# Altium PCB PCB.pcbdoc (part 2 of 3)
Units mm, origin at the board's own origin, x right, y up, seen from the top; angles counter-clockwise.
Board outline 65.2 x 64.45 mm, 2 copper layers (Top Layer, Bottom Layer); 194 components, 135 nets, 803 pads, 401 vias.
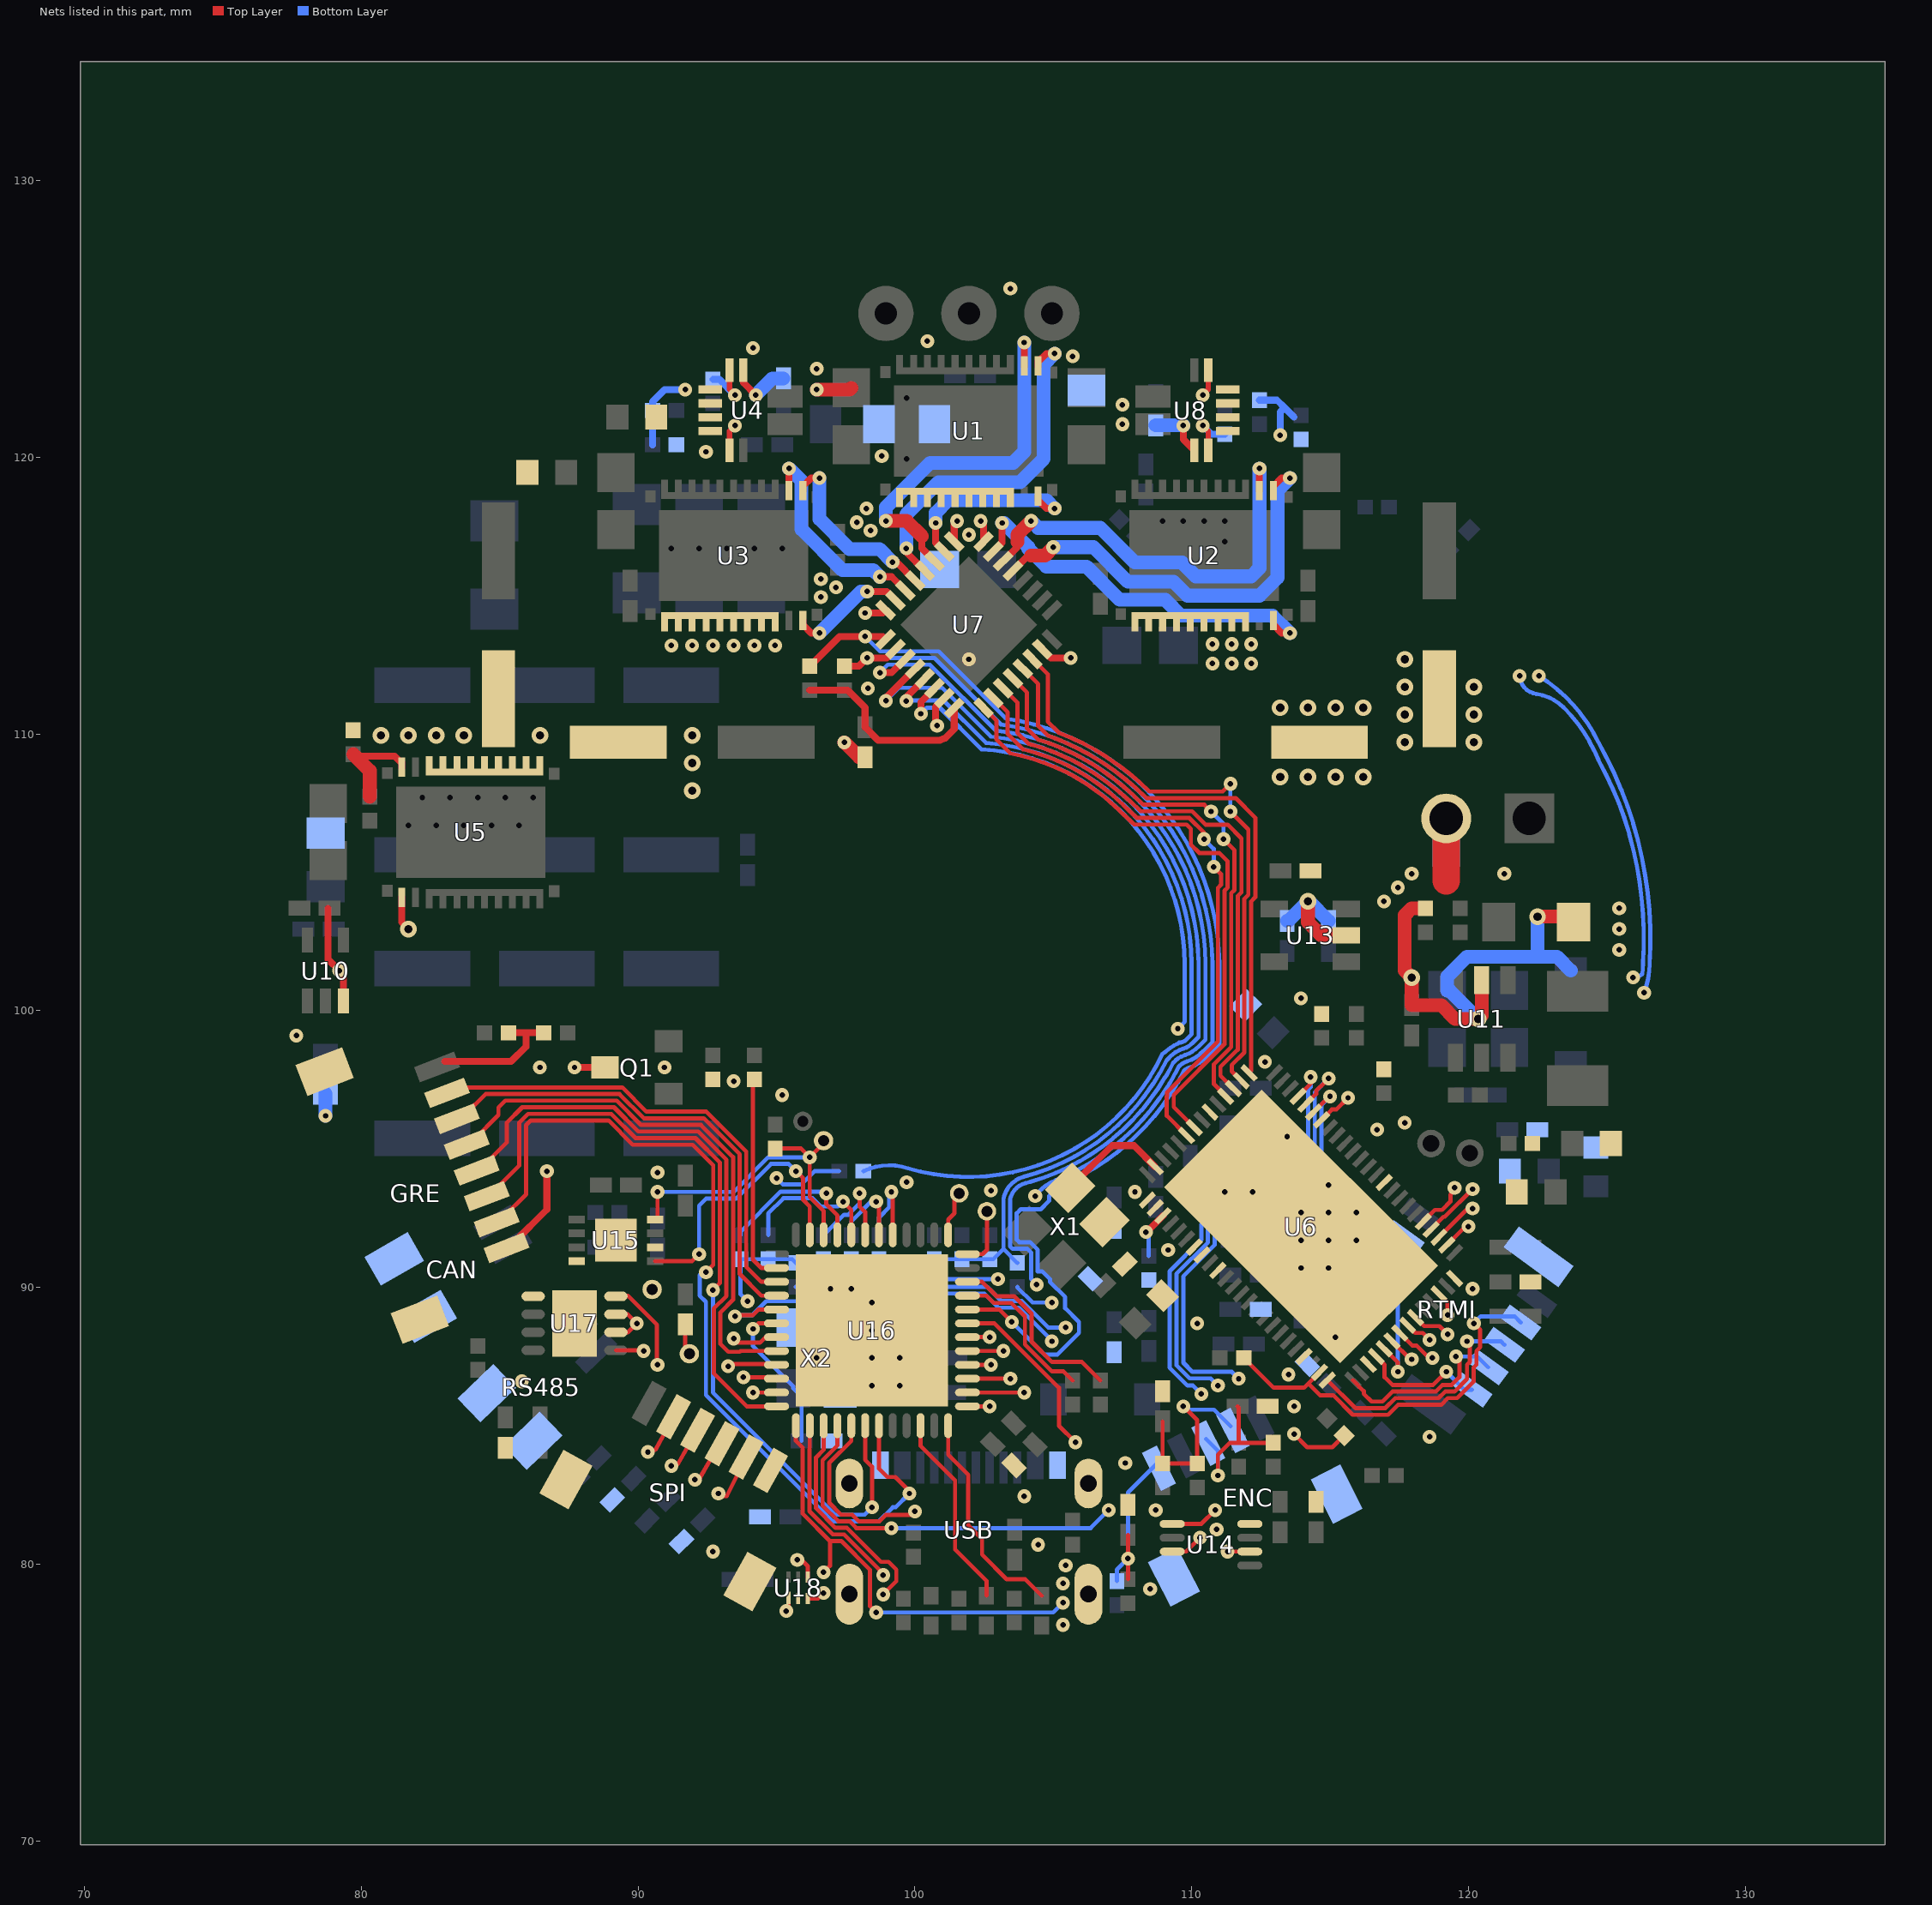
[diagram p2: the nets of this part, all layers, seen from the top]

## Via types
v1: diameter 0.5, hole 0.2, Top Layer to Bottom Layer, 297 vias
v2: diameter 0.6, hole 0.3, Top Layer to Bottom Layer, 104 vias

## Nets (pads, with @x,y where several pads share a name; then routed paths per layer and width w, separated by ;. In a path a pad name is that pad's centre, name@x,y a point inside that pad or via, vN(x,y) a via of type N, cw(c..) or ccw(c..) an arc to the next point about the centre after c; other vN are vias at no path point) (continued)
CAN_RX: pad.4 R58.1 U15.4 U16.46 | length 12.4
  Top Layer w0.15: U15.4@90.618,92.45 90.7,92.532 v1(90.7,93.45) ; R58.1@94.95,95.017 95.883,95.017 v1(96.2,94.7) ; U16.46@96.7,91.899 96.7,92.762 96.2,93.262 v1(96.2,94.7) ; pad.4@96.7,95.45 96.7,95.2 v1(96.2,94.7)
  Bottom Layer w0.15: v1(90.7,93.45) 93.45,93.45 94.7,94.7 v1(96.2,94.7)
CAN_TX: U16.47 | length 10.2
  Top Layer w0.15: 90.618,90.95 91.95,90.95 v1(92.2,91.2) ; v1(95.7,94.2) 95.961,93.939 95.961,93.163 96.2,92.924 U16.47@96.2,91.899
  Bottom Layer w0.15: v1(92.2,91.2) 92.2,92.95 92.461,93.211 93.549,93.211 94.799,94.461 95.439,94.461 v1(95.7,94.2)
CS_2: SPI.2 U16.25 | length 19.2
  Top Layer w0.15: v1(90.35,84.05) 90.623,84.129 SPI.2@91.31,85.374 ; U16.25@101.95,85.7 v1(102.7,85.7)
  Mid-Layer 1 w0.15: v1(90.35,84.05) 93.613,84.05 96.707,80.957 98.757,80.957 98.891,80.823 99.634,80.823 102.7,83.889 v1(102.7,85.7)
CSNA: R16.1 U6.19 | length 38.7
  Top Layer w0.15: U6.19@118.369,92.377 118.793,92.8 119.05,92.8 119.35,93.1 119.35,93.35 119.5,93.5 v1(119.5,93.6)
  Mid-Layer 2 w0.15: v1(113.2,120.8) 113.45,121.05 cw(c101.978,101.874) 120.55,114.3 cw(c116.909,111.333) 121.3,113 cw(c121.072,112.833) 121.331,112.719 ccw(c121.928,112.122) 121.149,112.447 ccw(c121.928,112.122) 121.194,111.704 ccw(c121.928,112.122) 121.261,111.603 ccw(c122.679,112.705) 121.7,111.2 ccw(c122.453,112.357) 122.2,111 cw(c121.82,108.962) 122.86,110.755 cw(c122.13,109.771) 123.193,110.381 cw(c122.707,110.102) 123.214,110.34 cw(c113.922,107.883) 123.264,110.143 cw(c113.922,107.883) 123.533,107.949 123.533,97.633 120.899,94.999 120.899,94.663 120.311,94.075 119.975,94.075 v1(119.5,93.6)
  Bottom Layer w0.25: R16.1@112.45,122.066 113.084,122.066 113.355,121.795 ; v1(113.2,120.8) 113.2,121.641 113.355,121.795 ; 113.7,121.45 113.355,121.795
CSNC: R11.1 U6.17 | length 63.6
  Top Layer w0.15: U6.17@118.935,91.811 119.974,92.85 v1(120.15,92.85)
  Mid-Layer 2 w0.15: v1(91.7,122.45) 93.02,122.45 ; 93.023,122.448 93.02,122.45 ; v1(120.15,92.85) 120.65,93.35 120.65,93.738 121.377,94.465 121.377,94.777 124.011,97.411 124.011,107.95 ccw(c113.922,107.883) 122.95,112.387 cw(c124.124,113.374) 122.8,112.6 ccw(c101.792,101.474) 108.291,124.341 ccw(c114.792,117.757) 108.25,124.3 106.85,122.9 98.662,122.9 97.612,123.95 94.862,123.95 93.662,122.75 93.32,122.75 93.02,122.45
  Bottom Layer w0.25: 90.517,120.45 R11.1@90.517,121.7 90.517,122.017 90.95,122.45 v1(91.7,122.45)
CSPA: U6.18 U8.11 | length 40.6
  Top Layer w0.15: U6.18@118.652,92.094 118.652,92.102 119.1,92.55 119.15,92.55 v1(120.15,93.55)
  Top Layer w0.2: v1(110.4,122.25) 110.6,122.45 U8.11@110.6,123.15
  Mid-Layer 2 w0.15: v1(110.4,122.25) 110.8,122.65 cw(c110.8,111.676) 110.867,122.65 cw(c101.865,101.702) 121,114.1 ; v1(120.15,93.55) 120.15,93.576 121.138,94.564 121.138,94.888 123.772,97.522 123.772,107.95 ccw(c113.922,107.883) 123.496,110.199 ccw(c113.921,107.883) 123.44,110.42 ccw(c122.707,110.102) 123.4,110.5 ccw(c122.13,109.771) 122.45,111.2 cw(c122.897,113.197) 121.45,111.75 cw(c121.928,112.122) 121.5,112.55 ccw(c121.219,112.831) 121.55,113.05 ccw(c116.681,111.169) 121,114.1
CSPC: U4.11 U6.16 | length 62.9
  Top Layer w0.15: U6.16@119.218,91.528 119.89,92.2 v1(120,92.2)
  Top Layer w0.2: U4.11@93.3,120.25 93.3,120.95 v1(93.5,121.15)
  Mid-Layer 1 w0.15: v1(93.5,121.15) 92.95,121.7 92.95,122.7 94.15,123.9 v1(94.15,123.95)
  Mid-Layer 2 w0.15: v1(94.15,123.95) 94.524,123.95 94.774,124.2 97.7,124.2 98.75,123.15 106.75,123.15 108.211,124.611 cw(c101.763,101.367) 122.95,112.9 cw(c113.922,107.883) 124.25,107.95 124.25,97.312 121.616,94.678 121.616,94.366 120.889,93.639 120.889,93.251 120.65,93.012 120.65,92.65 120.2,92.2 v1(120,92.2)
CUR_SENSE_FAULT: U16.29 U18.4 | length 15.2
  Top Layer w0.15: v1(95.75,80.15) 95.9,80.15 96.129,79.921 U18.4@96.129,79.533 ; U16.29@101.899,87.701 v1(103.199,87.701)
  Mid-Layer 2 w0.15: v1(95.75,80.15) 95.75,83.25 96.95,84.45 100.45,84.45 101.7,85.7 101.7,86.825 102.575,87.7 v1@103.199,87.7
DBGSPI_CS: R43.1 RTMI.4 U6.75 | length 14.6
  Top Layer w0.15: R43.1@111.883,87.45 112.96,86.373 114.062,86.373 114.229,86.539 ; U6.75@114.622,86.932 114.229,86.539 ; v1(120.2,88.7) 120.427,88.473 120.427,87.838 120.289,87.7 120.289,87.201 120.189,87.101 120.189,86.588 119.596,85.995 119.258,85.995 119.019,85.756 117.457,85.756 117.096,85.395 115.821,85.395 115.114,86.102 114.635,86.102 114.229,86.508 114.229,86.539
  Bottom Layer w0.15: v1(120.2,88.7) 120.45,88.95 121.672,88.95 RTMI.4@121.891,88.731
DBGSPI_MISO: RTMI.10 U6.4 | length 4.6
  Top Layer w0.15: U6.4@116.672,87.498 116.973,87.197 116.973,86.752 117.252,86.473 118.723,86.473 v1(119.2,86.95)
  Bottom Layer w0.15: v1(119.2,86.95) 119.846,86.304 RTMI.10@120.128,86.304
DBGSPI_MOSI: RTMI.8 | length 6.7
  Top Layer w0.15: 115.824,86.649 116.223,86.251 116.223,86.152 116.502,85.873 116.898,85.873 117.259,86.234 118.822,86.234 119.06,86.473 119.398,86.473 119.677,86.752 119.677,87.373 v1(119.55,87.5)
  Bottom Layer w0.15: v1(119.55,87.5) 120.328,87.5 RTMI.8@120.716,87.113
DBGSPI_SCK: RTMI.6 U6.76 | length 8.8
  Top Layer w0.15: U6.76@114.905,86.649 115.92,85.634 116.997,85.634 117.358,85.995 118.921,85.995 119.159,86.234 119.497,86.234 119.95,86.687 119.95,87.2 120.05,87.3 120.05,87.95 v1(119.95,88.05)
  Bottom Layer w0.15: v1(119.95,88.05) 121.175,88.05 RTMI.6@121.304,87.922
DBGSPI_TRG: RTMI.3 U6.5 | length 6.3
  Top Layer w0.15: U6.5@116.955,87.781 117.45,87.286 v1(117.45,86.95)
  Bottom Layer w0.15: v1(117.45,86.95) 117.45,89.7 118.067,90.317 118.067,91.405 RTMI.3@117.684,91.787
DE: U16.9 U17.2 U17.3 | length 8.1
  Top Layer w0.15: U17.2@89.195,88.375 89.625,88.375 v1(89.95,88.7) 89.625,89.025 U17.3@89.195,89.025 ; v1(93.25,87.15) 93.327,87.227 94.973,87.227 U16.9@95.001,87.2
  Mid-Layer 2 w0.15: v1(89.95,88.7) 89.95,88.625 91.675,86.9 93.125,86.9 93.402,87.177 93.277,87.177 v1(93.25,87.15)
DIAG_1: U16.22 | length 7.1
  Top Layer w0.15: U16.22@100.2,85.001 100.2,84.275 101.45,83.025 101.45,80.525 102.584,79.39 102.584,78.854
DIAG_2: U16.24 | length 7.9
  Top Layer w0.15: U16.24@101.201,84.951 101.201,83.95 101.928,83.223 101.928,81.397 102.427,80.898 102.427,80.341 103.318,79.45 103.988,79.45 104.584,78.854
DVDD: U7.24 | length 7.3
  Top Layer w0.25: 98.2,110.245 98.673,109.773 100.902,109.773 101.096,109.851 101.42,110.174 U7.24@101.42,110.945
  Top Layer w0.254: 96.2,111.584 97.566,111.584 98.2,110.95 98.2,110.245
ENC_A: U6.35 U14.7 | length 23.5
  Top Layer w0.15: U14.7@109.297,80.45 109.8,80.45 v1(110.3,80.95) ; U6.35@113.844,96.902 114.3,97.358 v1(114.3,97.6)
  Mid-Layer 1 w0.15: v1(110.3,80.95) 109.95,80.95 109.2,81.7 109.2,82.7 110.35,83.85 v1(110.35,86.15)
  Bottom Layer w0.15: v1(110.35,86.15) 110.05,86.45 109.849,86.45 109.2,87.099 109.2,90.576 110.35,91.725 110.35,92.275 110.752,92.678 112.34,92.678 114.211,94.549 114.211,97.149 114.3,97.238 v1(114.3,97.6)
ENC_A_5: ENC.5 R54.1 | length 6.4
  Top Layer w0.15: 107.7,79.45 v1(107.7,80.2) 107.7,81.05
  Bottom Layer w0.15: R54.1@107.3,79.383 107.3,79.8 v1(107.7,80.2) 107.7,82.581 ENC.5@108.737,83.619
ENC_B: U6.34 U14.5 | length 23.3
  Top Layer w0.15: U14.5@109.297,81.45 110.35,81.45 v1(110.85,81.95) ; U6.34@114.127,96.619 114.5,96.992 114.5,97.1 v1@114.8,97.4
  Mid-Layer 1 w0.15: v1(110.85,81.95) 111.45,82.55 111.45,86.2 111.2,86.45 v1(110.95,86.45)
  Bottom Layer w0.15: v1(110.95,86.45) 110.689,86.711 109.926,86.711 109.45,87.187 109.45,90.488 110.589,91.627 110.589,92.177 110.851,92.439 112.439,92.439 114.45,94.45 114.45,97.05 v1(114.95,97.55)
ENC_B_5: ENC.3 R52.1 | length 5.8
  Top Layer w0.15: v1(110.95,83.2) 110.95,83.95 111.383,84.383 111.7,84.383 ; 111.655,85.7 111.7,85.655 111.7,84.383 ; R52.1@112.95,84.383 111.7,84.383
  Bottom Layer w0.15: ENC.3@110.519,84.527 110.95,84.096 v1(110.95,83.2)
ENC_I: U6.33 U14.2 | length 23
  Top Layer w0.15: v1(111.3,80.45) U14.2@112.103,80.45 ; U6.33@114.41,96.336 114.973,96.9 v1(115,96.9)
  Mid-Layer 1 w0.15: v1(111.3,80.45) 111.7,80.85 v1(111.7,86.7)
  Bottom Layer w0.15: v1(111.7,86.7) 111.45,86.95 110.025,86.95 109.7,87.275 109.7,90.394 109.697,90.397 110.828,91.528 110.828,92.078 110.95,92.2 112.538,92.2 114.689,94.351 114.689,96.589 v1(115,96.9)
ENC_I_5: ENC.2 R50.1 R51.1 | length 7.1
  Top Layer w0.15: 108.95,85.155 R51.1@108.95,83.633 R50.1@110.2,83.633 110.2,85.2 v1(109.7,85.7)
  Bottom Layer w0.15: v1(109.7,85.7) 109.82,85.58 110.811,85.58 ENC.2@111.41,84.981
F_CLOCK: U6.51 X1.3 | length 4
  Top Layer w0.25: X1.3@105.609,93.597 105.609,93.609 107.124,95.124 107.915,95.124 U6.51@108.682,94.357
F_CS: R41.1 U6.6 U16.16 | length 36
  Top Layer w0.15: U16.16@97.2,85.001 97.2,84.288 96.664,83.752 96.664,82.112 97.23,81.546 97.638,81.546 97.885,81.3 v1(99.15,81.3) ; v1(113.7,84.7) 114.177,84.223 115.085,84.223 R41.1@115.506,84.644 ; U6.6@117.238,88.063 117.902,87.4 v1(117.95,87.4)
  Mid-Layer 1 w0.15: v1(107,81.95) 107.639,81.95 108.894,80.695 108.894,80.395 109.821,79.468 110.314,79.468 ccw(c106.164,95.236) 114.205,81.052 ccw(c105.243,92.657) 115.611,82.289 115.611,84.224 ; v1(113.7,84.7) 113.775,84.7 114.252,84.223 115.473,84.223 ; 115.474,84.224 115.611,84.224 ; v1(117.95,87.4) 117.95,86.563 115.611,84.224
  Bottom Layer w0.15: v1(99.15,81.3) 106.35,81.3 v1(107,81.95)
F_EN: U6.55 U16.30 | length 10.7
  Top Layer w0.15: U16.30@101.9,88.2 v1(102.7,88.2)
  Top Layer w0.25: v1(108.35,92) 108.376,92 U6.55@108.965,92.589
  Mid-Layer 2 w0.15: v1(102.7,88.2) 102.7,88.95 103.5,89.75 103.5,90.6 103.85,90.95 107.3,90.95 v1(108.35,92)
  Bottom Layer w0.15: v1(108.35,92) 108.45,91.9 108.45,91.133
F_STATUS: U6.12 U16.31 | length 29.5
  Top Layer w0.15: U16.31@101.899,88.699 102.876,88.699 105.203,86.372 105.203,84.997 v1(105.8,84.4) ; U6.12@118.935,89.761 119.25,89.446 v1(119.25,89)
  Mid-Layer 2 w0.15: v1(105.8,84.4) 106.211,84.4 106.997,83.614 106.997,82.828 110.56,79.266 110.68,79.266 ccw(c107.165,90.535) 110.904,79.338 ccw(c107.165,90.535) 112.319,79.915 ccw(c104.576,93.074) 115.372,82.278 115.372,86.373 117.354,88.355 117.842,88.355 118.303,88.816 119.066,88.816 v1(119.25,89)
FA: R5.1 U8.6 U18.1 | length 84.9
  Top Layer w0.15: v1(95.35,78.3) 95.358,78.3 95.429,78.371 U18.1@95.429,78.804
  Top Layer w0.2: v1(110.4,121.15) 110.6,120.95 U8.6@110.6,120.25
  Mid-Layer 1 w0.15: v1(95.35,78.3) 96.45,78.3 96.85,77.9 ccw(c97.55,78.425) 97.55,77.55 105.1,77.55 v1(105.35,77.8) ; v1(105.35,79.3) 105.35,79.375 104.973,79.752 104.973,80.148 105.741,80.916 107.997,80.916 108.416,80.497 108.416,80.197 109.674,78.939 110.171,78.939 ccw(c106.166,95.232) 110.201,78.946 ccw(c106.164,95.236) 118.031,83.369 118.047,83.383 ccw(c103.592,100.652) 118.169,83.486 ccw(c103.594,100.65) 126.005,98.469 ccw(c103.594,100.65) 126.094,99.779 ccw(c125.025,99.025) 125.95,99.95 cw(c126.575,100.575) 125.7,100.45 cw(c126.575,100.575) v1(125.95,101.2)
  Mid-Layer 2 w0.15: v1(105.35,77.8) 104.873,78.277 104.873,78.798 105.35,79.275 v1(105.35,79.3) ; v1(110.4,121.15) 109.777,121.773 109.502,121.773 109.223,122.052 109.223,122.973 109.6,123.35 109.75,123.35 cw(c101.847,101.662) 121.45,113.85 cw(c119.681,112.525) v1(121.85,112.1)
  Bottom Layer w0.15: v1(121.85,112.1) ccw(c122.549,112.143) 122.45,111.45 cw(c122.2,109.7) 123.45,110.95 cw(c119.472,106.972) 124.7,109.05 cw(c113.901,102.968) 126.084,105.246 cw(c112.091,102.57) 126.311,101.714 ; v1(125.95,101.2) ccw(c125.95,101.7) 126.285,101.328 ccw(c123.694,101.7) 126.311,101.7
  Bottom Layer w0.25: v1(110.4,121.15) 110.716,120.834 R5.1@111.2,120.834
FC: R3.1 U4.6 U18.3 | length 97.2
  Top Layer w0.15: U18.3@96.129,78.759 96.509,78.759 v1(96.7,78.95)
  Top Layer w0.2: U4.6@93.3,123.15 93.3,122.45 v1(93.5,122.25)
  Mid-Layer 1 w0.15: v1(105.45,79.95) 105.45,80.287 105.84,80.677 107.898,80.677 108.177,80.398 108.177,80.098 109.575,78.7 110.2,78.7 ccw(c106.164,95.236) 118.2,83.2 ccw(c103.594,100.65) v1(126.35,100.65)
  Mid-Layer 2 w0.15: v1(93.5,122.25) 94.95,123.7 97.5,123.7 98.55,122.65 106.95,122.65 108.35,124.05 cw(c114.665,117.736) 108.37,124.07 ; v1(96.7,78.95) 96.7,78.25 ccw(c97.55,78.416) 97.55,77.55 98.575,77.55 99.686,78.661 103.824,78.661 105.113,79.95 v1(105.45,79.95) ; 108.37,124.07 cw(c101.84,101.643) 122.26,112.983 cw(c120.757,112.001) v1(122.55,112.1)
  Bottom Layer w0.15: v1(122.55,112.1) cw(c119.449,107.159) 124.7,109.7 cw(c112.091,102.57) 126.55,101.7 cw(c123.694,101.7) v1(126.35,100.65)
  Bottom Layer w0.25: R3.1@92.7,122.816 92.934,122.816 v1(93.5,122.25)
GHA: U2.1 U7.5 | length 15.5
  Top Layer w0.25: U7.5@103.541,115.894 104.097,116.45 ; U2.1@112.95,118.8 112.95,118.95 113.25,119.25 v1(113.55,119.25)
  Top Layer w0.5: 104.2,116.45 104.7,116.45 v1(105,116.75)
  Bottom Layer w0.5: v1(105,116.75) 106.45,116.75 107.7,115.5 109.35,115.5 109.85,115 112.45,115 113.1,115.65 113.1,118.8 v1(113.55,119.25)
GHB: U1.1 U7.12 | length 13
  Top Layer w0.25: v1(99.687,116.708) 99.687,116.566 U7.12@100.359,115.894 ; U1.1@104.45,123.3 104.45,123.45 104.75,123.75 v1(105.05,123.75)
  Bottom Layer w0.5: v1(99.687,116.708) 99.687,117.937 100.85,119.1 103.8,119.1 104.65,119.95 104.65,123.35 v1(105.05,123.75)
GHC: U3.1 U7.13 | length 6.7
  Top Layer w0.25: U3.1@95.95,118.8 95.95,118.95 96.25,119.25 v1(96.55,119.25) ; v1(99.192,116.213) 99.334,116.213 U7.13@100.006,115.541
  Bottom Layer w0.5: v1(96.55,119.25) 96.55,117.768 97.632,116.686 98.719,116.686 v1(99.192,116.213)
GLA: U2.22 U7.7 | length 14.1
  Top Layer w0.25: U7.7@102.834,116.602 103.152,116.92 v1(103.152,117.627) ; U2.22@112.95,114.1 112.95,113.95 113.25,113.65 v1(113.55,113.65)
  Bottom Layer w0.5: v1(103.152,117.627) 103.223,117.627 104.1,116.75 104.1,116.7 104.75,116.05 106.2,116.05 107.4,114.85 109.05,114.85 109.623,114.277 112.923,114.277 v1(113.55,113.65)
GLB: U1.22 U7.10 | length 7
  Top Layer w0.25: v1(100.748,117.627) 100.748,116.92 U7.10@101.066,116.602 ; U1.22@104.45,118.6 104.45,118.45 104.75,118.15 v1(105.05,118.15)
  Bottom Layer w0.5: v1(100.748,117.627) 100.748,117.998 101.2,118.45 104.75,118.45 v1(105.05,118.15)
GLBR: U5.22 | length 3.7
  Top Layer w0.25: 79.767,109.2 81.2,109.2 81.45,108.95 U5.22@81.45,108.8
  Top Layer w0.5: 79.7,109.267 79.767,109.2 80.3,108.667 80.3,107.733
GLC: U3.22 U7.15 | length 4.4
  Top Layer w0.25: U3.22@95.95,114.1 95.95,113.95 96.25,113.65 v1(96.55,113.65) ; v1(98.273,115.152) 98.98,115.152 U7.15@99.298,114.834
  Bottom Layer w0.5: v1(96.55,113.65) 98.052,115.152 v1(98.273,115.152)
GND: C18.1 C21.1 C23.1 C24.1 C25.2 C26.2 C27.2 C28.2 C29.2 C30.1 C31.1 C32.1 C37.1 C38.1 C42.1 C44.1 C46.1 C48.1 C50.1 C52.1 C54.1 C55.1 C57.1 C58.1 C59.1 C60.1 C64.1 C65.1 C66.1 C67.1 C68.1 C69.1 C70.1 C71.1 C72.1 C74.1 C76.1 C78.1 C80.1 C82.1 C84.1 C86.1 C87.1 C89.1 C91.1 CAN.3 CAN.4 ENC.6 ENC.7 GRE.9 GRE.10 pad.1@96.45,87.45 pad.1@96.95,89.95 pad.1@97.7,89.95 pad.1@98.45,86.45 pad.1@98.45,87.45 pad.1@98.45,88.45 pad.1@98.45,89.45 pad.1@99.45,86.45 pad.1@99.45,87.45 pad.1@101.95,112.7 pad.1@111.2,93.45 pad.1@112.2,93.45 pad.1@113.45,95.45 pad.1@113.95,90.7 pad.1@113.95,91.7 pad.1@113.95,92.7 pad.1@114.95,90.7 pad.1@114.95,91.7 pad.1@114.95,92.7 pad.1@114.95,93.7 pad.1@115.2,88.2 pad.1@115.95,91.7 pad.1@115.95,92.7 pad.3@90.504,89.926 R1.1 R2.1 R4.1 R6.1 R7.1 R12.1 R13.1 R14.1 R15.1 R26.1 R28.1 R42.1 R46.1 RS485.3 RS485.4 RTMI.5 RTMI.7 RTMI.9 RTMI.12 SPI.6 SPI.7 SPI.8 U1.12 U1.13 U1.14 U1.15 U1.16 U1.17 U1.18 U1.19 U1.20 U2.12 U2.13 U2.14 U2.15 U2.16 U2.17 U2.18 U2.19 U2.20 U3.12 U3.13 U3.14 U3.15 U3.16 U3.17 U3.18 U3.19 U3.20 U4.5 U4.7 U4.8 U4.9 U4.10 U5.1 U5.12 U5.13 U5.14 U5.15 U5.16 U5.17 U5.18 U5.19 U5.20 U6.3 U6.14 U6.24 U6.44 U6.53 U6.54 U6.59 U6.60 U6.62 U6.73 U6.77 U7.8 U7.9 U7.16 U7.23 U7.31 U8.5 U8.7 U8.8 U8.9 U8.10 U9.2 U10.3 U11.2 U13.2 U14.4 U15.2 U15.8 U15.9 U16.49 U17.5 U17.9 U18.2 USB.1 USB.12 USB.13 USB.14 USB.15 USB.16 X1.2 X2.2 X2.4 | length 45.4
  Top Layer w0.25: 78.79,103.7 78.79,101.86 v1(79.2,101.45) 79.35,101.3 U10.3@79.35,100.35 ; U5.1@81.45,104.1 81.45,103.2 v2(81.7,102.95) ; U4.5@93.8,123.15 93.8,122.7 v1(94.25,122.25) ; v1(98.202,114.374) 98.839,114.374 U7.16@98.945,114.48 ; v1(100.8,110.3) 100.75,110.35 100.75,110.982 U7.23@101.066,111.298 ; U7.9@101.42,116.955 101.42,117.592 v1(101.526,117.698) ; v1(102.374,117.698) 102.481,117.592 U7.8@102.481,116.955 ; U7.31@104.602,113.066 104.92,112.748 v1(105.627,112.748) ; v1(109.7,121.15) 109.7,120.65 U8.5@110.1,120.25
  Top Layer w0.5: v1(96.45,122.45) 97.64,122.45 97.7,122.51 ; v1(97.45,109.7) 97.995,109.155 C21.1@98.2,109.155 ; v2(114.2,103.95) 114.2,103.2 114.677,102.723 U13.2@115.588,102.723 ; R13.1@118.45,103.7 117.95,103.7 117.7,103.45 117.7,101.45 v2(117.95,101.2) 117.95,100.2 119.021,100.2 119.521,99.7 v2(120.35,99.7) 120.48,99.83 U11.2@120.48,101.1 ; v2(122.5,103.4) 123.35,103.4 C29.2@123.55,103.2
  Top Layer w1: 119.2,104.7 U9.2@119.2,106.95
  Mid-Layer 1 w1: 119.2,104.7 U9.2@119.2,106.95
  Bottom Layer w0.5: v1(78.7,96.2) C72.1@78.7,97 ; v1(94.25,122.25) 94.85,122.85 C24.1@95.25,122.85 ; C23.1@108.7,121.155 109.695,121.155 v1(109.7,121.15) ; C31.1@113.45,103.245 113.495,103.245 v2(114.2,103.95) 114.245,103.95 C30.1@114.95,103.245 ; v2(120.35,99.7) 119.32,100.73 119.23,100.73 119.23,101.23 119.95,101.95 122.462,101.95 ; v2(122.5,103.4) 122.5,101.988 122.462,101.95 ; 123.7,101.45 123.2,101.95 122.462,101.95
  Bottom Layer w1: 119.2,105.289 U9.2@119.2,106.95
  other v1: 108.5,79.1 92.7,80.45 104.45,80.7 110.9,81.25 108.7,81.95 103.95,82.45 107.6,83.65 118.6,84.6 113.7,85.7 85.8,86.6 113.5,86.85 110.2,88.7 120.15,89.95 109.15,91.35 107.95,93.45 102.75,93.5 99.7,93.8 90.7,94.15 116.7,95.7 117.7,95.95 95.2,96.95 93.45,97.45 86.45,97.95 90.95,97.95 112.65,98.15 77.65,99.1 113.95,100.45 125.45,102.2 125.45,102.95 125.45,103.7 116.95,103.95 117.45,104.45 117.95,104.95 121.3,104.95 98.3,111.65 110.75,112.55 111.45,112.55 112.15,112.55 91.2,113.2 91.95,113.2 92.7,113.2 93.45,113.2 94.2,113.2 94.95,113.2 110.75,113.25 111.45,113.25 112.15,113.25 96.6,114.95 97.15,115.3 96.6,115.6 101.95,117.2 98.4,117.35 97.9,117.65 98.25,118.15 98.8,120.05 92.45,120.2 107.5,121.2 107.5,121.9 96.45,123.2 105.7,123.65 100.45,124.2 103.45,126.1
  other v2: 91.95,107.95 113.2,108.45 114.2,108.45 115.2,108.45 116.2,108.45 91.95,108.95 117.7,109.7 120.2,109.7 80.7,109.95 81.7,109.95 82.7,109.95 83.7,109.95 86.45,109.95 91.95,109.95 117.7,110.7 120.2,110.7 113.2,110.95 114.2,110.95 115.2,110.95 116.2,110.95 117.7,111.7 120.2,111.7 117.7,112.7
GR_D0: GRE.2 U16.3 | length 17
  Top Layer w0.15: GRE.2@83.361,97.227 89.423,97.227 90.3,96.35 92.464,96.35 93.906,94.909 93.906,90.744 94.45,90.2 U16.3@95.001,90.2
GR_D1: GRE.3 U16.4 | length 17.1
  Top Layer w0.15: GRE.3@83.719,96.293 83.793,96.293 84.488,96.988 89.324,96.988 90.201,96.111 92.365,96.111 93.667,94.81 93.667,90.483 94.45,89.7 U16.4@95.001,89.7
GR_D2: GRE.4 U16.8 | length 20
  Top Layer w0.15: GRE.4@84.078,95.358 84.95,96.23 84.95,96.499 85.2,96.749 89.225,96.749 90.102,95.872 92.266,95.872 93.428,94.711 93.428,89.553 92.973,89.098 92.973,87.952 93.252,87.673 93.673,87.673 93.7,87.7 U16.8@95.001,87.701
GR_D3: GRE.5 U16.12 | length 21.5
  Top Layer w0.15: GRE.5@84.437,94.424 85.25,95.238 85.25,95.95 85.81,96.51 89.126,96.51 90.003,95.633 92.167,95.633 93.189,94.612 93.189,89.689 92.734,89.234 92.734,86.891 93.925,85.7 U16.12@95.001,85.699
GR_D4: GRE.6 U16.18 | length 30.1
  Top Layer w0.15: GRE.6@84.794,93.492 85.7,94.398 85.7,95.95 86.021,96.271 89.027,96.271 89.904,95.394 92.068,95.394 92.95,94.513 92.95,90.15 v1(92.7,89.9) ; U16.18@98.201,85.001 98.201,83.77 98.45,83.521 v1(98.45,82.05)
  Bottom Layer w0.15: v1(92.7,89.9) 92.7,86.2 97.115,81.785 97.931,81.785 98.185,81.785 v1(98.45,82.05)
GR_D5: GRE.7 U16.19 | length 32.7
  Top Layer w0.15: GRE.7@85.154,92.561 85.95,93.357 85.95,95.862 86.12,96.032 88.928,96.032 89.805,95.156 91.969,95.156 92.711,94.414 92.711,90.811 v1(92.45,90.55) ; U16.19@98.699,85.001 98.699,83.451 99.005,83.145 99.289,83.145 99.8,82.634 v1(99.8,82.55)
  Bottom Layer w0.15: v1(92.45,90.55) 92.45,90.67 92.223,90.443 92.223,89.702 92.45,89.475 92.45,86.112 97.016,81.546 98.696,81.546 99.2,82.05 99.3,82.05 v1(99.8,82.55)
GR_EN: R47.1 U16.2 | length 7.5
  Top Layer w0.15: R47.1@94.2,97.517 94.145,97.462 94.145,91.005 94.45,90.7 U16.2@95.001,90.7
GR_GND: GRE.8 Q1.3 | length 8.3
  Top Layer w0.25: GRE.8@85.513,91.627 86.7,92.814 v1(86.7,94.2) ; v1(87.7,97.95) Q1.3@88.8,97.95
  Mid-Layer 2 w0.25: v1(86.7,94.2) 87.7,95.2 v1(87.7,97.95)
GR_V: R48.1 R49.1 | length 4.9
  Top Layer w0.25: 83.004,98.162 85.412,98.162 85.95,98.7 85.95,99.186 85.936,99.2 ; R48.1@85.316,99.2 85.936,99.2 ; R49.1@86.584,99.2 85.936,99.2
IDRIVE_0: U16.41 | length 3.3
  Top Layer w0.15: v1(99.15,93.45) 99.199,93.401 U16.41@99.199,91.899
  Bottom Layer w0.15: 98.7,91.883 98.7,92.525 99.077,92.902 99.077,93.377 v1(99.15,93.45)
IDRIVE_18: U16.42 | length 2.9
  Top Layer w0.15: v1(98.6,93.1) 98.699,93.001 U16.42@98.699,91.899
  Bottom Layer w0.15: 97.7,91.883 97.7,92.387 98.413,93.1 v1(98.6,93.1)
IDRIVE_75: U16.43 | length 3.7
  Top Layer w0.15: v1(98,93.4) 98,92.925 98.201,92.724 U16.43@98.201,91.899
  Bottom Layer w0.15: 96.7,91.883 97.44,92.623 97.598,92.623 98,93.025 v1(98,93.4)
INHA: U6.46 U7.25 | length 22.3
  Top Layer w0.15: U7.25@102.48,110.945 102.95,110.475 102.95,109.8 103.45,109.3 cw(c102.011,101.708) 105.814,108.435 cw(c100.427,99.477) 106.875,107.703 cw(c94.744,93.694) 107.848,106.798 107.922,106.728 109.816,106.728 109.973,106.572 109.973,106.002 110.275,105.7 111,105.7 111.3,105.4 111.3,104.452 111.189,104.341 111.189,102.211 111.189,98.789 109.35,96.95 109.35,96.517 U6.46@110.096,95.771
INHB: U6.41 U7.27 | length 20.8
  Top Layer w0.15: U7.27@103.187,111.652 103.7,111.139 103.7,110.05 104.1,109.65 cw(c101.9,101.51) 106.055,108.847 cw(c100.427,99.477) 108.156,107.206 110.014,107.206 110.497,106.723 111.303,106.723 111.8,106.225 111.8,104.277 111.667,104.143 111.667,101.733 111.667,98.591 111.044,97.968 111.044,97.652 U6.41@111.511,97.185
INHC: U6.39 U7.29 | length 20.6
  Top Layer w0.15: U7.29@103.895,112.359 104.45,111.803 104.45,110.292 104.792,109.95 cw(c101.517,100.835) 108.366,107.684 111.591,107.684 112.3,106.975 112.3,104.101 112.145,103.945 112.145,97.819 U6.39@112.076,97.751
INLA: U6.47 U7.26 | length 22.1
  Top Layer w0.15: U7.26@102.834,111.298 103.35,110.782 103.35,110 103.9,109.45 cw(c101.97,101.635) 105.934,108.641 cw(c100.427,99.477) 107.027,107.888 cw(c94.744,93.694) 108.017,106.967 109.915,106.967 110.45,106.432 v1(110.45,106.2) ; U6.47@109.813,95.488 109.1,96.202 109.1,96.9 109.111,96.911 109.111,97.049 110.95,98.888 110.95,102.45 110.95,104.44 111.061,104.551 111.061,104.939 v1(110.8,105.2)
  Bottom Layer w0.15: v1(110.45,106.2) 110.8,105.85 v1(110.8,105.2)
INLB: U6.42 U7.28 | length 20.8
  Top Layer w0.15: U7.28@103.541,112.005 104.05,111.497 104.05,110.2 104.45,109.8 cw(c101.8,101.309) 106.354,108.95 cw(c100.838,100.027) 108.255,107.445 110.455,107.445 v1(110.7,107.2) ; v1(111.15,106.2) 111.55,105.8 111.55,104.364 111.428,104.242 111.428,101.972 111.428,98.69 110.805,98.067 110.805,97.345 111.228,96.922 U6.42@111.228,96.902
  Bottom Layer w0.15: v1(110.7,107.2) 111.15,106.75 v1(111.15,106.2)
INLC: U6.40 U7.30 | length 21.4
  Top Layer w0.15: U7.30@104.248,112.713 104.8,112.161 104.8,110.45 105.198,110.052 ; 105.2,110.05 cw(c101.821,101.271) 108.473,107.923 111.123,107.923 v1(111.4,108.2) ; v1(111.4,107.2) 112.05,106.55 112.05,104.189 111.906,104.044 111.906,98.492 111.45,98.036 111.45,97.811 U6.40@111.793,97.468
  Bottom Layer w0.15: v1(111.4,107.2) v1(111.4,108.2)
M_CS: U16.17 | length 27.4
  Top Layer w0.15: U16.17@97.701,85.001 97.701,84.451 96.903,83.653 96.903,82.211 97.329,81.785 97.737,81.785 97.984,81.539 98.714,81.539 98.952,81.777 99.877,81.777 v1(100,81.9)
  Mid-Layer 1 w0.15: v1(95,93.95) 93.7,92.65 93.7,89.95 92.7,88.95 92.7,86.414 97.329,81.785 97.914,81.2 98.375,81.2 98.952,81.777 99.877,81.777 v1(100,81.9)
  Bottom Layer w0.15: v1(95,93.95) 95.227,93.723 95.898,93.723 96.375,94.2 97.267,94.2
M_CS/NC: R40.1 U7.21 | length 33.1
  Top Layer w0.25: v1(99.687,111.192) 99.687,111.334 U7.21@100.359,112.005
  Bottom Layer w0.15: R40.1@98.133,94.2 cw(c99.066,92.241) 99.75,94.3 ccw(c101.921,101.761) 108.95,98.45 ccw(c108.688,98.984) 109.091,98.547 cw(c110.04,97.519) 109.51,98.814 ; v1(99.687,111.192) 99.705,111.21 101.04,111.21 102.55,109.7 ccw(c114.419,121.569) 102.572,109.678 cw(c101.958,101.659) 110,101.7 110,99.15 109.8,98.95 cw(c109.558,99.192) 109.55,98.85 cw(c109.125,99.275) 109.51,98.814
M_EN: U6.32 U7.22 | length 27.1
  Top Layer w0.15: U6.32@114.693,96.054 115.066,96.427 115.227,96.427 v1(115.65,96.85)
  Top Layer w0.25: v1(100.218,110.733) 100.218,111.157 U7.22@100.713,111.652
  Mid-Layer 1 w0.15: v1(109.5,99.35) 113.85,99.35 115.65,97.55 v1(115.65,96.85)
  Bottom Layer w0.15: v1(100.218,110.733) 100.435,110.95 100.9,110.95 102.4,109.45 cw(c101.959,101.672) 109.75,101.7 109.75,99.6 v1(109.5,99.35)
M_FAULT: R8.1 U7.17 U16.32 | length 45.8
  Top Layer w0.15: U16.32@101.899,89.199 103.051,89.199 v1(103.5,88.75)
  Top Layer w0.25: v1(98.202,113.526) 98.839,113.526 U7.17@98.945,113.42
  Top Layer w0.254: R8.1@96.2,112.45 97.276,113.526 v1(98.202,113.526)
  Bottom Layer w0.15: v1(98.202,113.526) 98.741,112.987 100.863,112.987 103.25,110.6 ccw(c116.041,123.391) 103.293,110.557 cw(c101.948,101.605) 111,101.7 111,98.75 110.8,98.55 cw(c108.635,100.715) 110.466,98.261 cw(c109.687,99.213) 110.443,98.243 cw(c109.558,99.192) 109.949,97.954 ccw(c110.271,96.933) 109.828,97.908 ccw(c110.04,97.519) 109.729,97.835 cw(c101.903,101.783) 109.487,97.389 cw(c101.903,101.783) 109.326,97.121 cw(c101.902,101.784) 109.211,96.943 cw(c101.903,101.783) 105.214,93.667 ccw(c105.463,93.056) 104.85,93.3 104.85,93.125 104.548,92.823 103.823,92.823 103.678,92.678 103.678,91.722 103.768,91.632 104.163,91.632 104.436,91.359 104.436,90.577 104.598,90.577 104.877,90.298 104.877,90.198 105.427,89.648 105.427,89.248 105.927,88.748 105.927,88.352 105.148,87.573 104.677,87.573 v1(103.5,88.75)
M_MISO/MODE: R9.1 R29.1 R30.1 R34.1 U7.18 | length 50.3
  Top Layer w0.25: v1(98.273,112.748) 98.981,112.748 U7.18@99.299,113.066
  Top Layer w0.254: R9.1@97.45,112.45 97.975,112.45 v1(98.273,112.748)
  Mid-Layer 1 w0.15: v1(93.95,89.5) 93.95,92.2 94.973,93.223 95.448,93.223 96.775,94.55 97.05,94.55 cw(c97.901,93.696) 98.25,94.85 ccw(c102.076,102.878) 103.15,94.05 cw(c103.131,93.413) 103.7,93.7 ccw(c104.35,94.028) v1(104.35,93.3)
  Bottom Layer w0.15: v1(93.95,89.5) 93.7,89.75 R34.1@93.7,91.017 R30.1@94.7,91.017 95.566,91.017 R29.1@95.7,90.883 ; v1(98.273,112.748) 100.702,112.748 103.1,110.35 ccw(c116.193,123.444) 103.108,110.342 cw(c101.951,101.62) 110.75,101.7 110.75,98.85 110.55,98.65 cw(c109.394,99.806) 110.404,98.521 cw(c109.55,99.5) 110.347,98.473 cw(c109.687,99.213) 110.288,98.425 cw(c109.558,99.192) 109.851,98.175 ccw(c110.04,97.519) 109.806,98.16 ccw(c110.04,97.519) 109.735,98.129 ccw(c110.04,97.519) 109.531,97.973 cw(c101.903,101.783) 109.281,97.508 cw(c101.903,101.783) 109.124,97.248 cw(c101.903,101.783) 105.082,93.871 ccw(c105.708,92.314) v1(104.35,93.3)
M_MOSI/IDRIVE: R31.1 R32.1 R33.1 R35.1 U7.19 | length 42.5
  Top Layer w0.25: v1(98.733,112.218) 99.157,112.218 U7.19@99.652,112.713
  Mid-Layer 1 w0.15: v1(103,90.3) 104.2,90.3 v1(104.4,90.1)
  Bottom Layer w0.15: R35.1@96.7,91.017 R33.1@97.7,91.017 R32.1@98.7,91.017 99.566,91.017 R31.1@99.7,90.883 ; v1(98.733,112.218) 99.024,112.509 100.541,112.509 102.9,110.15 ccw(c115.783,123.033) 102.926,110.124 cw(c101.954,101.633) 110.5,101.7 110.5,98.95 110.3,98.75 cw(c109.55,99.5) 110.194,98.657 cw(c109.687,99.213) 110.133,98.607 cw(c109.558,99.192) 109.785,98.404 ccw(c110.04,97.519) 109.724,98.384 ccw(c110.04,97.519) 109.33,98.106 cw(c101.903,101.783) 109.074,97.628 cw(c88.36,118.342) 109.037,97.591 cw(c101.896,101.773) 104.167,93.815 cw(c101.896,101.773) 103.998,93.769 ccw(c104.193,93.024) 103.439,93.178 103.439,91.482 103.528,91.393 104.064,91.393 104.197,91.26 104.197,90.303 v1(104.4,90.1) ; R31.1@99.95,90.7 100.35,90.3 v1(103,90.3)
M_SCK/VDS: R36.1 R37.1 R38.1 R39.1 U7.20 | length 35.8
  Top Layer w0.25: v1(98.95,111.2) 98.95,111.303 U7.20@100.006,112.359
  Bottom Layer w0.15: v1(98.95,111.2) 99.42,111.67 100.98,111.67 102.7,109.95 ccw(c114.348,121.598) 102.748,109.903 cw(c101.956,101.647) 110.25,101.7 110.25,99.05 110.05,98.85 cw(c109.687,99.213) 109.978,98.79 109.969,98.781 cw(c109.558,99.192) 109.719,98.634 ccw(c110.04,97.519) 109.128,98.235 cw(c83.809,123.556) 109.096,98.204 cw(c101.896,101.773) 103.937,94 ccw(c104.193,93.024) 103.2,93.2 103.2,91.383 ; R39.1@100.7,91.017 R38.1@101.7,91.017 R37.1@102.7,91.017 102.834,91.017 103.2,91.383 ; R36.1@103.7,90.883 103.2,91.383
MISO: U6.9 U16.14 | length 58.8
  Top Layer w0.15: 96.2,84.2 96.186,84.186 96.186,81.914 97.032,81.068 97.441,81.068 98.85,79.659 v1(98.85,79.6) ; 96.2,84.2 U16.14@96.2,85.001 ; U6.9@118.087,88.912 118.398,88.6 118.95,88.6 v1(119.25,88.3)
  Mid-Layer 2 w0.15: v1(98.85,79.6) v1@98.85,79.575 ; v1(104.95,88.05) 104.95,85.2 99.325,79.575 v1@98.85,79.575 ; v1(119.25,88.3) 119.075,88.3 118.798,88.577 118.402,88.577 117.941,88.116 117.453,88.116 115.611,86.274 115.611,82.039 cw(c106.375,91.275) 112.479,79.727 cw(c107.165,90.535) 110.68,79.016 110.472,79.016 108.572,80.916 105.403,80.916 103.626,79.139 99.286,79.139 v1@98.85,79.575
  Bottom Layer w0.15: 95.7,90.017 96.017,90.017 96.45,90.45 98.95,90.45 99.203,90.197 99.203,89.64 99.336,89.507 100.064,89.507 100.336,89.778 102.509,89.778 103.019,89.268 103.757,89.268 104.95,88.075 v1(104.95,88.05)
MISO_2: SPI.4 U16.27 | length 20.1
  Top Layer w0.15: v1(92.05,83.05) 92.216,83.094 SPI.4@92.935,84.34 ; U16.27@101.899,86.7 v1(103.45,86.7)
  Mid-Layer 1 w0.15: v1(92.05,83.05) 93.9,83.05 96.471,80.479 98.559,80.479 98.693,80.345 99.832,80.345 103.178,83.691 103.178,85.165 103.416,85.403 103.416,85.997 103.189,86.224 103.189,86.439 v1(103.45,86.7)
MODE_0: U16.44 | length 5.2
  Top Layer w0.15: v1(97.4,93.1) 97.701,92.799 U16.44@97.701,91.899
  Bottom Layer w0.15: 94.7,91.883 94.7,92.675 95.247,93.222 96.303,93.222 96.602,92.923 97.223,92.923 v1(97.4,93.1)
MODE_45: U16.45 | length 5.5
  Top Layer w0.15: v1(96.8,93.4) 96.8,93 97.2,92.599 U16.45@97.2,91.899
  Bottom Layer w0.15: 93.7,91.883 93.7,92.013 95.148,93.461 96.739,93.461 v1(96.8,93.4)
MOSI: U6.8 U16.15 | length 56.6
  Top Layer w0.15: U16.15@96.7,85.001 96.7,84.126 96.425,83.851 96.425,82.013 97.131,81.307 97.54,81.307 98.77,80.077 99.048,80.077 99.327,79.798 99.327,79.377 v1(98.85,78.9) ; U6.8@117.804,88.629 118.083,88.35 118.35,88.35 v1(118.6,88.1)
  Mid-Layer 2 w0.15: v1(105.45,88.55) 104.775,88.55 104.473,88.248 104.473,87.852 104.711,87.614 104.711,85.299 99.49,80.077 98.652,80.077 98.373,79.798 98.373,79.402 98.85,78.925 v1(98.85,78.9) 103.725,78.9 105.502,80.677 108.473,80.677 110.45,78.7 ccw(c107.165,90.535) 115.85,81.85 115.85,86.175 117.552,87.877 118.377,87.877 v1(118.6,88.1)
  Bottom Layer w0.15: 99.7,90.017 102.608,90.017 103.118,89.507 103.856,89.507 104.813,88.55 v1(105.45,88.55)
MOSI_2: SPI.3 U16.28 | length 20.5
  Top Layer w0.15: v1(91.2,83.55) 91.432,83.615 SPI.3@92.136,84.86 ; U16.28@101.899,87.2 v1(102.75,87.2)
  Mid-Layer 1 w0.15: v1(91.2,83.55) 93.775,83.55 96.608,80.718 96.681,80.719 ; 96.682,80.718 98.658,80.718 98.792,80.584 99.733,80.584 102.939,83.79 102.939,85.264 103.177,85.502 103.177,85.898 102.75,86.325 v1(102.75,87.2)
NRST: C85.1 pad.3@91.85,87.6 U16.7 | length 4.6
  Top Layer w0.15: C85.1@91.7,88.655 91.7,87.75 pad.3@91.85,87.6 ; v1(93.45,88.15) 93.6,88 94.4,88 94.601,88.201 U16.7@95.001,88.201
  Mid-Layer 2 w0.15: pad.3@91.85,87.6 92.4,88.15 v1(93.45,88.15)
OSC_IN: U16.5 X2.3 | length 8.4
  Top Layer w0.15: v1(93.5,88.95) 93.55,89 94.15,89 94.349,89.199 U16.5@95.001,89.199
  Bottom Layer w0.15: v1(93.5,88.95) 93.55,89 94.125,89 94.625,89.5 96.35,89.5 X2.3@97.3,88.55 97.677,88.927 99.178,88.927 99.405,88.7
OSC_OUT: U16.6 | length 5.7
  Top Layer w0.15: v1(94.15,88.5) 94.349,88.699 U16.6@95.001,88.699
  Bottom Layer w0.15: v1(94.15,88.5) 94.15,87.875 95.6,86.425 95.6,86.35 95.905,86.045 95.905,84.45
RX: U16.11 | length 6.8
  Top Layer w0.15: 89.195,87.725 90.175,87.725 v1(90.2,87.7) ; v1(94.15,86.2) U16.11@95.001,86.2
  Mid-Layer 2 w0.15: v1(90.2,87.7) 90.223,87.677 90.223,87.002 90.825,86.4 93.225,86.4 93.402,86.223 94.127,86.223 v1(94.15,86.2)
SCK: U6.7 U16.13 | length 55.7
  Top Layer w0.15: U16.13@95.699,85.001 95.7,84.45 95.947,84.203 95.947,81.815 96.933,80.829 ; v1(96.7,79.7) 96.933,79.933 96.933,80.829 ; v1(98.6,78.25) 98.373,78.477 98.373,79.799 97.342,80.829 96.933,80.829 ; U6.7@117.521,88.346 117.967,87.9 118.125,87.9 118.575,87.45 v1(118.7,87.45)
  Mid-Layer 1 w0.15: v1(105.35,78.6) 105.35,78.625 104.734,79.241 104.734,80.247 105.642,81.155 108.096,81.155 108.655,80.596 108.655,80.296 109.773,79.178 110.143,79.178 ccw(c106.164,95.236) 114.966,81.228 ccw(c108.898,87.797) 115.199,81.451 ccw(c-63.795,261.746) 115.85,82.1 115.85,84.125 118.189,86.464 118.189,86.939 v1(118.7,87.45)
  Mid-Layer 2 w0.15: v1(96.7,79.7) 96.789,79.7 97.405,80.316 99.391,80.316 104.472,85.398 104.472,87.515 104.234,87.753 104.234,88.709 104.95,89.425 v1(104.95,89.45)
  Bottom Layer w0.15: v1(98.6,78.25) 105,78.25 v1(105.35,78.6) ; 103.7,90.017 103.7,90.001 104.251,89.45 v1(104.95,89.45)
SCK_2: SPI.5 U16.26 | length 19.8
  Top Layer w0.15: v1(92.9,82.55) 93,82.45 93.2,82.45 SPI.5@93.903,83.866 ; U16.26@101.899,86.2 v1(103.95,86.2)
  Mid-Layer 1 w0.15: v1(92.9,82.55) 94.05,82.55 96.36,80.24 98.46,80.24 98.594,80.106 99.931,80.106 103.417,83.592 103.417,85.066 103.655,85.304 103.655,85.905 v1(103.95,86.2)
SHA: U2.2 U7.6 | length 15.5
  Top Layer w0.25: U7.6@103.188,116.248 103.7,116.76 103.7,116.95 ; U2.2@112.45,118.8 v1(112.45,119.6)
  Top Layer w0.5: 103.7,116.95 103.7,117.2 v1(104.2,117.7)
  Bottom Layer w0.5: v1(104.2,117.7) 104.45,117.45 106.7,117.45 107.95,116.2 109.65,116.2 110.15,115.7 112.15,115.7 112.45,116 v1(112.45,119.6)
SHB: U1.2 U7.11 | length 13.7
  Top Layer w0.25: 100.25,117.15 100.25,116.711 U7.11@100.713,116.248 ; U1.2@103.95,123.3 v1(103.95,124.15)
  Top Layer w0.5: v1(98.95,117.7) 99.7,117.7 100.25,117.15
  Bottom Layer w0.5: v1(98.95,117.7) 98.95,118.2 100.55,119.8 103.55,119.8 103.95,120.2 v1(103.95,124.15)
SHC: U3.2 U7.14 | length 7.9
  Top Layer w0.25: U3.2@95.45,118.8 v1(95.45,119.6) ; v1(98.733,115.682) 99.157,115.682 U7.14@99.652,115.187
  Bottom Layer w0.5: v1(95.45,119.6) 95.898,119.152 95.898,117.404 97.378,115.924 98.491,115.924 v1(98.733,115.682)
SWCLK: pad.2@101.6,93.4 U16.37 | length 1.6
  Top Layer w0.15: U16.37@101.201,91.949 101.201,92.451 101.427,92.677 101.427,93.227 pad.2@101.6,93.4
SWDIO: pad.1@102.6,92.75 U16.36 | length 2.2
  Top Layer w0.15: U16.36@101.949,91.201 102.451,91.201 102.6,91.35 pad.1@102.6,92.8
TX: U16.10 U17.4 | length 8
  Top Layer w0.15: U17.4@89.195,89.675 89.22,89.7 89.625,89.7 90.677,88.648 90.677,87.223 v1(90.7,87.2) ; v1(93.8,86.75) 94.951,86.75 U16.10@95.001,86.7
  Mid-Layer 2 w0.15: v1(90.7,87.2) 91.25,86.65 93.7,86.65 v1(93.8,86.75)
USB_DM: U16.33 | length 5.7
  Top Layer w0.15: U16.33@101.899,89.7 102.587,89.7 102.849,89.438 103.487,89.438 103.977,88.948 103.977,87.936 104.95,86.964 105.369,86.964 105.7,86.633
USB_DP: U16.34 | length 6.9
  Top Layer w0.15: U16.34@101.899,90.2 102.425,90.2 102.948,89.677 103.586,89.677 104.216,89.047 104.216,88.035 104.95,87.301 106.031,87.301 106.7,86.633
